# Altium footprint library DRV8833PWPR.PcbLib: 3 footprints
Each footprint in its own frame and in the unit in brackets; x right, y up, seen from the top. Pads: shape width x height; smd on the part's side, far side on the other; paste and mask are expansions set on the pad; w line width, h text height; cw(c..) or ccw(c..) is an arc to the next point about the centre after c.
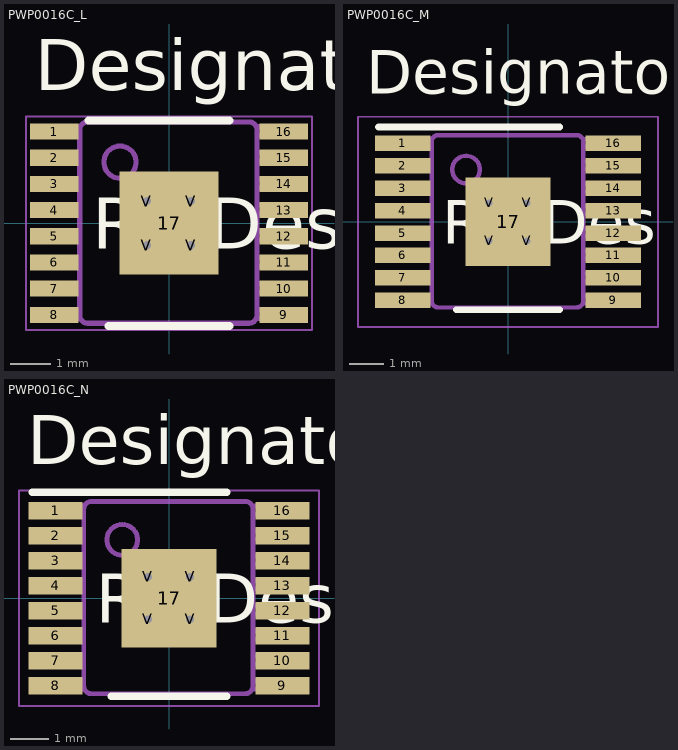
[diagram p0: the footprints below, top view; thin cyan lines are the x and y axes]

## PWP0016C_L [mm]
pads (21):
  rect 1.2x0.4 smd paste+0 mask+0.051: 1(-2.85,2.275) 2(-2.85,1.625) 3(-2.85,0.975) 4(-2.85,0.325) 5(-2.85,-0.325) 6(-2.85,-0.975) 7(-2.85,-1.625) 8(-2.85,-2.275) 9(2.85,-2.275) 10(2.85,-1.625) 11(2.85,-0.975) 12(2.85,-0.325) 13(2.85,0.325) 14(2.85,0.975) 15(2.85,1.625) 16(2.85,2.275)
  rect 2.46x2.56 smd paste+0 mask+0.051: 17(0,0)
  round 0.5 / inner round 1.524 / far side round 0.5 hole 0.203 paste-0.25 mask+0.051: V(-0.55,-0.55) V(-0.55,0.55) V(0.55,-0.55) V(0.55,0.55)
Top Overlay:
  lines w0.2: -2,2.55 1.5,2.55 ; -1.5,-2.55 1.5,-2.55
  text "Designator17" at -3.327,3.302 h1.27
  text "RefDes" at -1.905,-0.635 h1.27
Mechanical 13:
  drawing of 202 lines, arcs and shapes, not listed
Mechanical 15:
  lines w0.05: -3.55,-2.65 -3.55,2.65 3.55,2.65 3.55,-2.65 -3.55,-2.65
  lines w0.1: -0.5,0 0.5,0 ; 0,-0.5 0,0.5

## PWP0016C_M [mm]
pads (21):
  rect 1.6x0.45 smd paste+0 mask+0.051: 1(-3.05,2.275) 2(-3.05,1.625) 3(-3.05,0.975) 4(-3.05,0.325) 5(-3.05,-0.325) 6(-3.05,-0.975) 7(-3.05,-1.625) 8(-3.05,-2.275) 9(3.05,-2.275) 10(3.05,-1.625) 11(3.05,-0.975) 12(3.05,-0.325) 13(3.05,0.325) 14(3.05,0.975) 15(3.05,1.625) 16(3.05,2.275)
  rect 2.46x2.56 smd paste+0 mask+0.051: 17(0,0)
  round 0.5 / inner round 1.524 / far side round 0.5 hole 0.203 paste-0.25 mask+0.051: V(-0.55,-0.55) V(-0.55,0.55) V(0.55,-0.55) V(0.55,0.55)
Top Overlay:
  lines w0.2: -3.75,2.75 1.5,2.75 ; -1.5,-2.55 1.5,-2.55
  text "Designator16" at -4.115,3.708 h1.27
  text "RefDes" at -1.905,-0.635 h1.27
Mechanical 13:
  drawing of 202 lines, arcs and shapes, not listed
Mechanical 15:
  lines w0.05: -4.35,-3.05 -4.35,3.05 4.35,3.05 4.35,-3.05 -4.35,-3.05
  lines w0.1: -0.5,0 0.5,0 ; 0,-0.5 0,0.5

## PWP0016C_N [mm]
pads (21):
  rect 1.4x0.45 smd paste+0 mask+0.051: 1(-2.95,2.275) 2(-2.95,1.625) 3(-2.95,0.975) 4(-2.95,0.325) 5(-2.95,-0.325) 6(-2.95,-0.975) 7(-2.95,-1.625) 8(-2.95,-2.275) 9(2.95,-2.275) 10(2.95,-1.625) 11(2.95,-0.975) 12(2.95,-0.325) 13(2.95,0.325) 14(2.95,0.975) 15(2.95,1.625) 16(2.95,2.275)
  rect 2.46x2.56 smd paste+0 mask+0.051: 17(0,0)
  round 0.5 / inner round 1.524 / far side round 0.5 hole 0.203 paste-0.25 mask+0.051: V(-0.55,-0.55) V(-0.55,0.55) V(0.55,-0.55) V(0.55,0.55)
Top Overlay:
  lines w0.2: -3.55,2.75 1.5,2.75 ; -1.5,-2.55 1.5,-2.55
  text "Designator15" at -3.683,3.48 h1.27
  text "RefDes" at -1.905,-0.635 h1.27
Mechanical 13:
  drawing of 202 lines, arcs and shapes, not listed
Mechanical 15:
  lines w0.05: -3.9,-2.8 -3.9,2.8 3.9,2.8 3.9,-2.8 -3.9,-2.8
  lines w0.1: -0.5,0 0.5,0 ; 0,-0.5 0,0.5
